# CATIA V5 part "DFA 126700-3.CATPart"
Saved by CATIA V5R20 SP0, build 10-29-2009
Part number: DFA 126700-3
Revision: ANY
Definition: UNKNOWN
Nomenclature: DFA 126700-3
Source: Unknown
Bounding box of the stored display mesh (mm): x -3.264 to 3.264, y -2.475 to 2.475, z -3 to 3
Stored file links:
  C:\Users\Utente\Desktop\IO LAVORO\3D X SITO CF\CUMSA\3D files FA\FA 126712-21\DFA 126700-3.CATPart
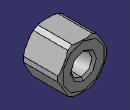
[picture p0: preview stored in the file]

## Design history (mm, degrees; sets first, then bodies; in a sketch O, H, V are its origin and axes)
Body1 "Chaflán4" (main body)
  Solid1: solid without history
